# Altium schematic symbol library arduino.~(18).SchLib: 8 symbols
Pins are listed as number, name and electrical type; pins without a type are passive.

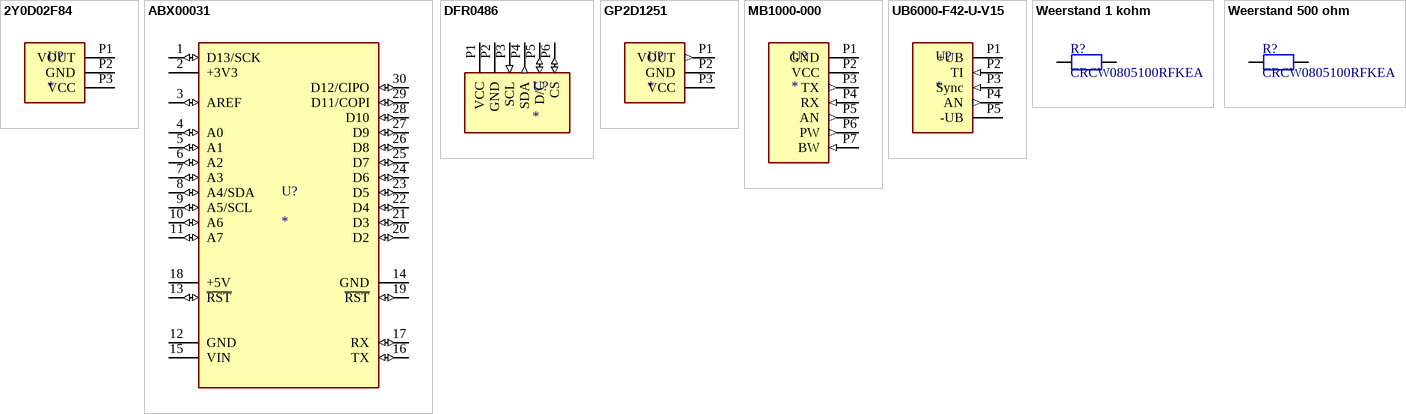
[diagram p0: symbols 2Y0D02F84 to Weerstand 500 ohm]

## 2Y0D02F84
designator U?
SENSOR OPTICAL ANALOG; MP: GP2D120; MF: Sharp
footprint GP2DXX
pins: P1 VOUT (power), P2 GND (power), P3 VCC (power)

## ABX00031
designator U?
Arduino Nano 33 BLE; MP: ABX00030
footprint MODULE_ABX00030
pins: 1 D13/SCK (io), 2 +3V3 (power), 3 AREF (io), 4 A0 (io), 5 A1 (io), 6 A2 (io), 7 A3 (io), 8 A4/SDA (io), 9 A5/SCL (io), 10 A6 (io), 11 A7 (io), 12 GND (power), 13 ~{RST} (io), 14 GND (power), 15 VIN (power), 16 TX (io), 17 RX (io), 18 +5V (power), 19 ~{RST} (io), 20 D2 (io), 21 D3 (io), 22 D4 (io), 23 D5 (io), 24 D6 (io), 25 D7 (io), 26 D8 (io), 27 D9 (io), 28 D10 (io), 29 D11/COPI (io), 30 D12/CIPO (io)

## DFR0486
designator U?
0.96" 128x64 OLED(V1.0) display DFROBOT; MP: GP2D120; MF: Sharp
footprint GP2DXX
pins: P1 VCC (power), P2 GND (power), P3 SCL (in), P4 SDA (out), P5 D/C (io), P6 CS (io)

## GP2D1251
designator U?
SENSOR OPTICAL ANALOG; MP: GP2D120; MF: Sharp
footprint GP2DXX
pins: P1 VOUT (out), P2 GND (power), P3 VCC (power)

## MB1000-000
designator U?
Analog ultrasonic sensor; MP: GP2D120; MF: Sharp
footprint GP2DXX
pins: P1 GND (power), P2 VCC (power), P3 TX (out), P4 RX (in), P5 AN (out), P6 PW (out), P7 BW (in)

## UB6000-F42-U-V15
designator U?
Ultrasonic sensor; MP: GP2D120; MF: Sharp
footprint GP2DXX
pins: P1 +UB (power), P2 TI (in), P3 Sync (in), P4 AN (out), P5 -UB (power)

## Weerstand 1 kohm
designator R?, comment CRCW0805100RFKEA
Manufacturer: Vishay Dale
footprint Weerstand 1M ohm
pins: 1, 2
1 alternate drawing of the same symbol

## Weerstand 500 ohm
designator R?, comment CRCW0805100RFKEA
Manufacturer: Vishay Dale
footprint Weerstand 1M ohm
pins: 1, 2
1 alternate drawing of the same symbol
